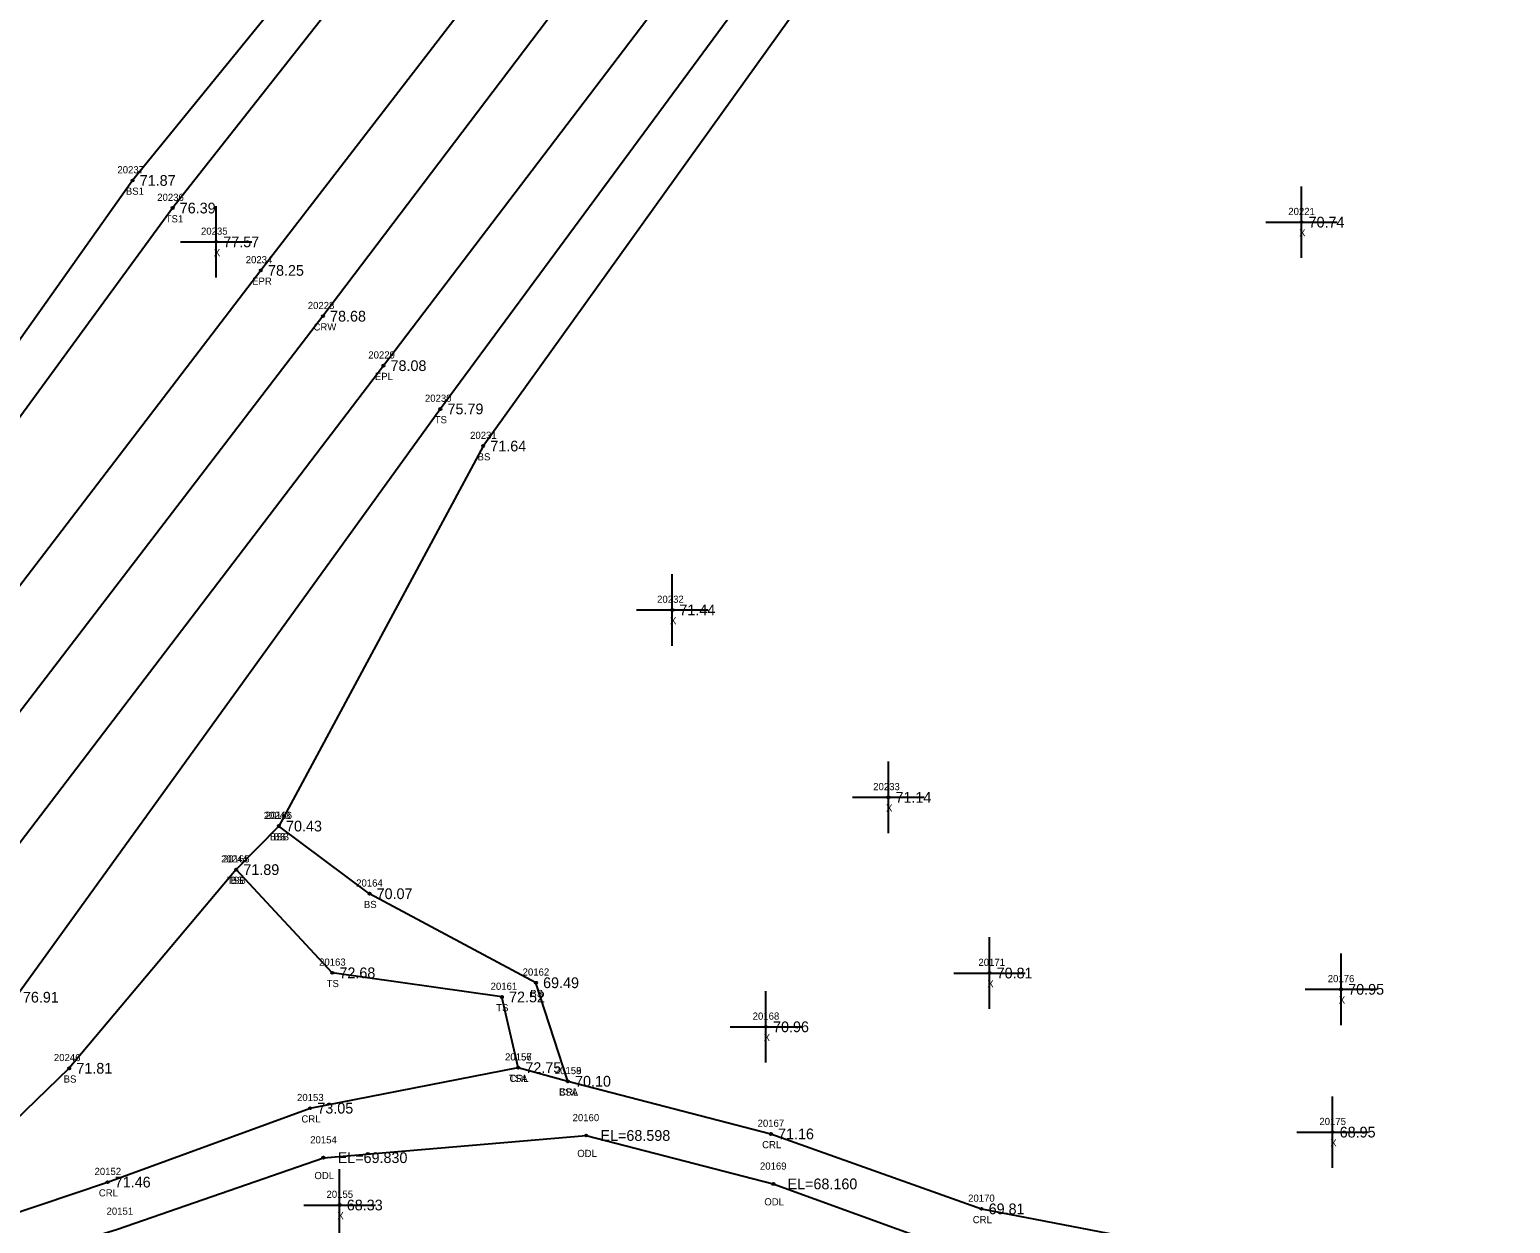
# Model space of a CAD drawing. Extents: x 2505300 to 2506184, y 912965 to 913825.
# Drawn here: x 2505870.9 to 2506078.1, y 913522.7 to 913689.6 of the extents above; entities that cross this region are included whole.
import ezdxf

# ---------------------------------------------------------------- set-up
doc = ezdxf.new("R2010")
doc.units = 0
for name, color, linetype in [('RD_DTM_BkLn1', 7, 'Continuous'), ('RD_DTM_BkLn2', 7, 'Continuous'), ('RD_DTM_BkLn_txCode', 7, 'Continuous'), ('RD_EX_H2O', 7, 'Continuous'), ('RD_EX_H2O_txCode', 7, 'Continuous'), ('RD_EX_Misc', 7, 'Continuous'), ('RD_EX_Misc_txCode', 7, 'Continuous'), ('RD_EX_Road', 7, 'Continuous'), ('RD_EX_Road_txCode', 7, 'Continuous'), ('RD_EX_TX_H2O_ELEV', 7, 'Continuous'), ('RD_EX_TX_Misc_ELEV', 7, 'Continuous'), ('RD_EX_TX_Road_ELEV', 7, 'Continuous'), ('RD_HC_Survey_ELEV', 7, 'Continuous'), ('RD_HC_Survey_txCode', 7, 'Continuous'), ('RD_SMD_Locator', 7, 'Continuous')]:
    doc.layers.add(name, color=color, linetype=linetype)

msp = doc.modelspace()

# ---------------------------------------------------------------- linework, layer by layer
at = {"layer": 'RD_DTM_BkLn1'}
msp.add_lwpolyline([(2506032.26, 913807.16), (2505970.46, 913726.68), (2505911.98, 913649.53), (2505850.51, 913569.34), (2505823.85, 913534.92)], dxfattribs=at)
at = {"layer": 'RD_DTM_BkLn2'}
for points in [[(2506003.2, 913816.23), (2505946.13, 913743.18), (2505885.35, 913668.51), (2505838.59, 913602.48), (2505816.98, 913593.69), (2505806.53, 913576.86), (2505793.9, 913560.45)], [(2506016.9, 913814.52), (2505950.1, 913739.73), (2505890.95, 913664.65), (2505842.78, 913598.78), (2505826.57, 913582.25), (2505819.44, 913586.46), (2505803.76, 913558.88), (2505804.05, 913552.09), (2505810.12, 913545.7)], [(2506050.33, 913797.99), (2506032.99, 913763.99), (2505986.64, 913715.48), (2505928.41, 913636.56), (2505869.01, 913554.3), (2505845.62, 913525.11), (2505838.24, 913524.07)], [(2506063.24, 913729.37), (2506038.62, 913753.69), (2505991.68, 913711.2), (2505934.4, 913631.37), (2505905.82, 913578.23), (2505899.85, 913572.14), (2505876.49, 913544.36), (2505856.4, 913524.92), (2505848.42, 913517.19)], [(2505946.25, 913542.54), (2505941.78, 913556.32), (2505918.49, 913568.77), (2505905.82, 913578.23)], [(2505939.3, 913544.45), (2505937.02, 913554.33), (2505913.29, 913557.71), (2505899.85, 913572.14)]]:
    msp.add_lwpolyline(points, dxfattribs=at)
at = {"layer": 'RD_EX_H2O'}
for points in [[(2505785.34, 913689.17), (2505760.31, 913663.21), (2505743.1, 913648.56), (2505723.59, 913620.14), (2505672.59, 913632.18), (2505661.09, 913622.14), (2505712.19, 913587.82), (2505787.26, 913549.76), (2505800.1, 913534.14), (2505825.87, 913510.39), (2505850.5, 913511.75), (2505883.26, 913521.88), (2505912.04, 913531.86), (2505948.81, 913534.96), (2505974.98, 913528.19), (2506003.87, 913517.71), (2506051.32, 913503.49), (2506114.3, 913484.75), (2506121.45, 913493.97), (2506156, 913550.08)], [(2505762.26, 913658.11), (2505746.15, 913644.25), (2505726.47, 913615.21), (2505674.21, 913628.01), (2505666.25, 913620.58), (2505714.6, 913592.15), (2505793.9, 913560.45), (2505801.32, 913552.8), (2505803.7, 913539.77), (2505832.63, 913516.96), (2505848.42, 913517.19), (2505881.86, 913528.44), (2505910.2, 913538.78), (2505939.3, 913544.45), (2505946.25, 913542.54), (2505974.65, 913535.18), (2506004.11, 913524.7), (2506052.03, 913515.47), (2506115.49, 913494.68), (2506138.05, 913548.89)]]:
    msp.add_lwpolyline(points, dxfattribs=at)
at = {"layer": 'RD_EX_Misc'}
for p, q in [((2506048.87, 913657.68), (2506048.87, 913667.68)), ((2505897.04, 913654.92), (2505897.04, 913664.92)), ((2506043.87, 913662.68), (2506053.87, 913662.68)), ((2505892.04, 913659.92), (2505902.04, 913659.92)), ((2505960.85, 913603.45), (2505960.85, 913613.45)), ((2505955.85, 913608.45), (2505965.85, 913608.45)), ((2505991.08, 913577.25), (2505991.08, 913587.25)), ((2505986.08, 913582.25), (2505996.08, 913582.25)), ((2506005.23, 913552.68), (2506005.23, 913562.68)), ((2506054.41, 913550.4), (2506054.41, 913560.4)), ((2506000.23, 913557.68), (2506010.23, 913557.68)), ((2505973.95, 913545.16), (2505973.95, 913555.16)), ((2506049.41, 913555.4), (2506059.41, 913555.4)), ((2505968.95, 913550.16), (2505978.95, 913550.16)), ((2506053.22, 913530.43), (2506053.22, 913540.43)), ((2506048.22, 913535.43), (2506058.22, 913535.43)), ((2505914.32, 913520.24), (2505914.32, 913530.24)), ((2505909.32, 913525.24), (2505919.32, 913525.24))]:
    msp.add_line(p, q, dxfattribs=at)
at = {"layer": 'RD_EX_Road'}
for points in [[(2506024.03, 913813.1), (2505962.01, 913732.06), (2505903.3, 913655.93), (2505840.88, 913574.4), (2505819.41, 913546.54), (2505814.19, 913542.64)], [(2506040.71, 913800.23), (2505979.73, 913720.47), (2505920.44, 913642.61), (2505859.42, 913562.61), (2505835.44, 913531.43), (2505833.77, 913527.25)]]:
    msp.add_lwpolyline(points, dxfattribs=at)
at = {"layer": 'RD_SMD_Locator'}
for centre in [(2505885.35, 913668.51), (2505890.95, 913664.65), (2506048.87, 913662.68), (2505897.04, 913659.92), (2505903.3, 913655.93), (2505911.98, 913649.53), (2505920.44, 913642.61), (2505928.41, 913636.56), (2505934.4, 913631.37), (2505960.85, 913608.45), (2505991.08, 913582.25), (2505905.82, 913578.23), (2505905.82, 913578.23), (2505899.85, 913572.14), (2505899.85, 913572.14), (2505918.49, 913568.77), (2505913.29, 913557.71), (2505941.78, 913556.32), (2506005.23, 913557.68), (2505937.02, 913554.33), (2506054.41, 913555.4), (2505973.95, 913550.16), (2505876.49, 913544.36), (2505939.3, 913544.45), (2505939.3, 913544.45), (2505946.25, 913542.54), (2505946.25, 913542.54), (2505910.2, 913538.78), (2505948.81, 913534.96), (2505974.65, 913535.18), (2506053.22, 913535.43), (2505912.04, 913531.86), (2505881.86, 913528.44), (2505974.98, 913528.19), (2505914.32, 913525.24), (2506004.11, 913524.7)]:
    msp.add_circle(centre, 0.15, dxfattribs=at)

# ---------------------------------------------------------------- texts
at = {"layer": 'RD_DTM_BkLn_txCode'}
for s, p in [('20237', (2505883.23, 913669.51)), ('BS1', (2505884.41, 913666.51)), ('20236', (2505888.8, 913665.65)), ('TS1', (2505889.99, 913662.65)), ('20230', (2505926.25, 913637.56)), ('TS', (2505927.62, 913634.56)), ('20231', (2505932.57, 913632.37)), ('BS', (2505933.62, 913629.37)), ('20243', (2505903.7, 913579.23)), ('20166', (2505903.94, 913579.23)), ('BSB', (2505904.57, 913576.23)), ('BS', (2505905.04, 913576.23)), ('20244', (2505897.73, 913573.14)), ('20165', (2505897.99, 913573.14)), ('TSB', (2505898.58, 913570.14)), ('BS', (2505899.07, 913570.14)), ('20164', (2505916.63, 913569.77)), ('BS', (2505917.71, 913566.77)), ('20163', (2505911.44, 913558.71)), ('TS', (2505912.5, 913555.71)), ('20162', (2505939.92, 913557.32)), ('20161', (2505935.44, 913555.33)), ('BS', (2505941, 913554.32)), ('TS', (2505936.22, 913552.33)), ('20246', (2505874.34, 913545.36)), ('20157', (2505937.47, 913545.45)), ('20159', (2505944.42, 913543.54)), ('BS', (2505875.71, 913542.36)), ('TSA', (2505938.02, 913542.45)), ('BSA', (2505944.99, 913540.54))]:
    msp.add_text(s, height=1, dxfattribs=at).set_placement(p)
at = {"layer": 'RD_EX_H2O_txCode'}
for s, p in [('20156', (2505937.45, 913545.45)), ('20158', (2505944.42, 913543.54)), ('CRL', (2505938.08, 913542.45)), ('20153', (2505908.36, 913539.78)), ('CRL', (2505945.03, 913540.54)), ('20160', (2505946.91, 913536.96)), ('CRL', (2505908.97, 913536.78)), ('20167', (2505972.79, 913536.18)), ('20154', (2505910.2, 913533.86)), ('CRL', (2505973.42, 913533.18)), ('ODL', (2505947.56, 913531.96)), ('20152', (2505880.03, 913529.44)), ('ODL', (2505910.79, 913528.86)), ('20169', (2505973.12, 913530.19)), ('CRL', (2505880.63, 913526.44)), ('ODL', (2505973.73, 913525.19)), ('20170', (2506002.24, 913525.7)), ('20151', (2505881.71, 913523.88)), ('CRL', (2506002.88, 913522.7))]:
    msp.add_text(s, height=1, dxfattribs=at).set_placement(p)
at = {"layer": 'RD_EX_Misc_txCode'}
for s, p in [('20221', (2506047.03, 913663.68)), ('20235', (2505894.92, 913660.92)), ('X', (2506048.55, 913660.68)), ('X', (2505896.72, 913657.92)), ('20232', (2505958.73, 913609.45)), ('X', (2505960.53, 913606.45)), ('20233', (2505988.96, 913583.25)), ('X', (2505990.76, 913580.25)), ('20171', (2506003.68, 913558.68)), ('X', (2506004.92, 913555.68)), ('20176', (2506052.55, 913556.4)), ('X', (2506054.09, 913553.4)), ('20168', (2505972.1, 913551.16)), ('X', (2505973.64, 913548.16)), ('20175', (2506051.38, 913536.43)), ('X', (2506052.9, 913533.43)), ('20155', (2505912.48, 913526.24)), ('X', (2505914, 913523.24))]:
    msp.add_text(s, height=1, dxfattribs=at).set_placement(p)
at = {"layer": 'RD_EX_Road_txCode'}
for s, p in [('20234', (2505901.18, 913656.93)), ('EPR', (2505902.07, 913653.93)), ('20229', (2505918.33, 913643.61)), ('EPL', (2505919.24, 913640.61))]:
    msp.add_text(s, height=1, dxfattribs=at).set_placement(p)
at = {"layer": 'RD_EX_TX_H2O_ELEV'}
for s, p in [('72.75', (2505940.3, 913543.7)), ('70.10', (2505947.25, 913541.79)), ('73.05', (2505911.2, 913538.03)), ('71.16', (2505975.65, 913534.43)), ('EL=68.598', (2505950.81, 913534.21)), ('EL=69.830', (2505914.04, 913531.11)), ('71.46', (2505882.86, 913527.69)), ('EL=68.160', (2505976.98, 913527.44)), ('69.81', (2506005.11, 913523.95))]:
    msp.add_text(s, height=1.5, dxfattribs=at).set_placement(p)
at = {"layer": 'RD_EX_TX_Misc_ELEV'}
for s, p in [('71.87', (2505886.35, 913667.76)), ('76.39', (2505891.95, 913663.9)), ('70.74', (2506049.87, 913661.93)), ('77.57', (2505898.04, 913659.17)), ('75.79', (2505929.41, 913635.81)), ('71.64', (2505935.4, 913630.62)), ('71.44', (2505961.85, 913607.7)), ('71.14', (2505992.08, 913581.5)), ('70.43', (2505906.82, 913577.48)), ('70.43', (2505906.82, 913577.48)), ('71.89', (2505900.85, 913571.39)), ('71.89', (2505900.85, 913571.39)), ('70.07', (2505919.49, 913568.02)), ('72.68', (2505914.29, 913556.96)), ('69.49', (2505942.78, 913555.57)), ('70.81', (2506006.23, 913556.93)), ('76.91', (2505870.01, 913553.55)), ('72.52', (2505938.02, 913553.58)), ('70.95', (2506055.41, 913554.65)), ('70.96', (2505974.95, 913549.41)), ('71.81', (2505877.49, 913543.61)), ('72.75', (2505940.3, 913543.7)), ('70.10', (2505947.25, 913541.79)), ('68.95', (2506054.22, 913534.68)), ('68.33', (2505915.32, 913524.49))]:
    msp.add_text(s, height=1.5, dxfattribs=at).set_placement(p)
at = {"layer": 'RD_EX_TX_Road_ELEV'}
for s, p in [('78.25', (2505904.3, 913655.18)), ('78.08', (2505921.44, 913641.86))]:
    msp.add_text(s, height=1.5, dxfattribs=at).set_placement(p)
at = {"layer": 'RD_HC_Survey_ELEV'}
msp.add_text('78.68', height=1.5, dxfattribs=at).set_placement((2505912.98, 913648.78))
at = {"layer": 'RD_HC_Survey_txCode'}
for s, p in [('20228', (2505909.86, 913650.53)), ('CRW', (2505910.66, 913647.53))]:
    msp.add_text(s, height=1, dxfattribs=at).set_placement(p)

doc.saveas('drawing.dxf')
